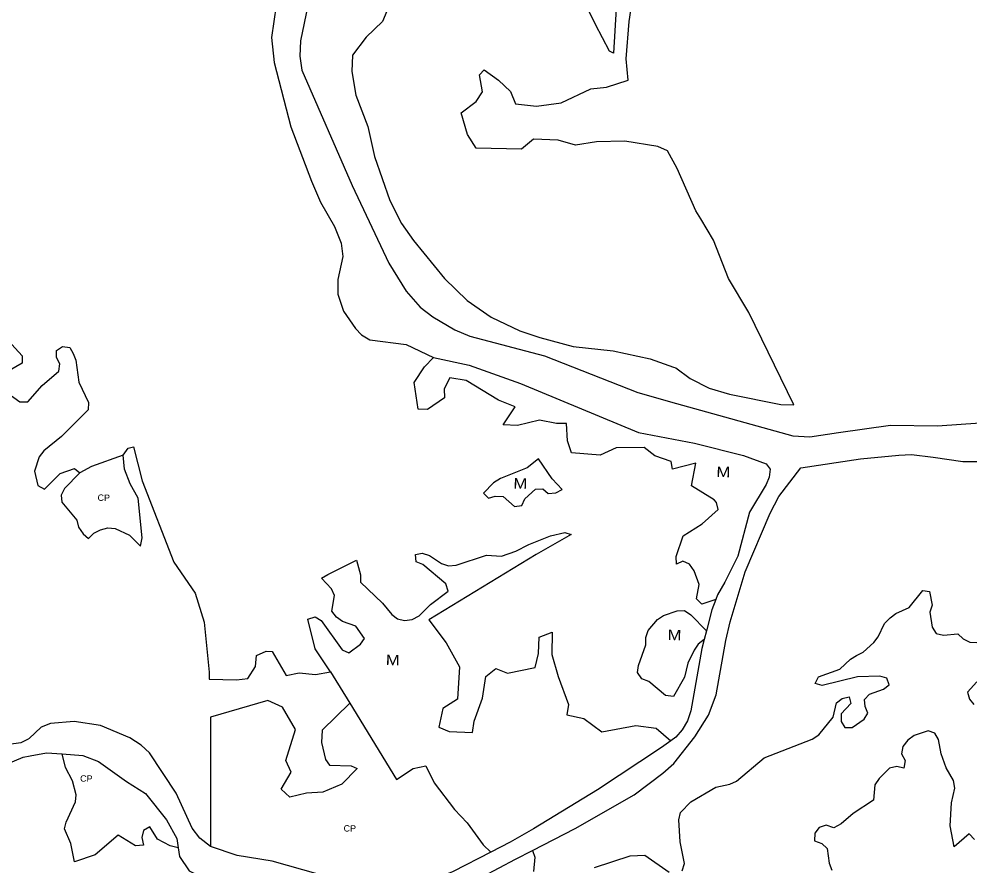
# Model space of a CAD drawing. Extents: x 713589 to 726391, y 7177764 to 7191819.
# Drawn here: x 718159 to 719111, y 7179355 to 7180202 of the extents above; entities that cross this region are included whole.
import ezdxf
from ezdxf.enums import TextEntityAlignment as Align

# ---------------------------------------------------------------- set-up
doc = ezdxf.new("R2010")
doc.units = 0
doc.header["$LTSCALE"] = 2.6
doc.layers.add('63', color=7, linetype='Continuous', lineweight=25)

msp = doc.modelspace()

# ---------------------------------------------------------------- linework, layer by layer
at = {"layer": '63'}
msp.add_line((718846.75, 7179590.09), (718844.48, 7179581.34), dxfattribs=at)
for points in [[(718765.06, 7180358.02), (718753.62, 7180167.91), (718749.67, 7180170), (718735.81, 7180196.62), (718723.68, 7180221.01)], [(718530.19, 7180218.08), (718522.62, 7180199.65), (718506.16, 7180183.86), (718492.67, 7180166.09), (718492.01, 7180149.64), (718495.95, 7180125.94), (718507.79, 7180094.68), (718514.7, 7180064.73), (718529.83, 7180020.64), (718541.67, 7179997.6), (718553.51, 7179980.49), (718584.77, 7179942.64), (718607.14, 7179920.59), (718631.16, 7179903.8), (718660.12, 7179890.3), (718679.86, 7179883.39), (718713.42, 7179874.5), (718753.57, 7179870.21), (718790.42, 7179862.31), (718813.86, 7179853.89), (718816.09, 7179853.09), (718830.57, 7179842.56), (718849.65, 7179832.68), (718869.72, 7179826.75), (718921.06, 7179816.54), (718934.29, 7179816.22), (718889.15, 7179908.36), (718868.76, 7179942.59), (718853.95, 7179980.76), (718841.11, 7180002.18), (718836.19, 7180010.38), (718817.44, 7180052.51), (718807.9, 7180070.28), (718798.03, 7180074.56), (718765.12, 7180079.83), (718736.82, 7180079.17), (718715.76, 7180075.89), (718698.32, 7180080.83), (718673.64, 7180081.82), (718661.79, 7180071.95), (718616.38, 7180072.94), (718607.5, 7180086.44), (718601.25, 7180108.16), (718616.39, 7180119.67), (718622.64, 7180129.21), (718619.68, 7180146.33), (718624.29, 7180151.26), (718638.77, 7180141.06), (718650.61, 7180129.54), (718655.55, 7180117.36), (718676.61, 7180115.05), (718701.29, 7180118.34), (718730.91, 7180132.16), (718746.7, 7180133.8), (718768.42, 7180141.03), (718766.31, 7180162.46), (718769.31, 7180199.74), (718776.89, 7180248.44)], [(718417.78, 7180225.72), (718416.02, 7180215.6), (718411.5, 7180183.76), (718414.1, 7180158.63), (718430.81, 7180094.32), (718451.52, 7180039.92), (718460.36, 7180018.74), (718474.48, 7179994.61), (718481.19, 7179977.94), (718482.95, 7179964.54), (718477.85, 7179941.62), (718478, 7179926.8), (718483.38, 7179909.83), (718495.38, 7179892.46), (718501.65, 7179886), (718510.02, 7179881), (718546.1, 7179876.34), (718573.47, 7179863.35)], [(718447.7, 7180215.62), (718440.47, 7180180.39), (718439.95, 7180165.08), (718441.96, 7180150.95), (718492.24, 7180035.69), (718528.81, 7179958), (718546.27, 7179929.79), (718560.1, 7179914.01), (718573.06, 7179904.29), (718594.95, 7179891.09), (718609.89, 7179884.69), (718684.7, 7179865.16), (718777.95, 7179828.53), (718816.94, 7179817.6), (718933.11, 7179785.01), (718950.1, 7179784.17), (718978.88, 7179788.48), (719030.92, 7179795.77), (719078.16, 7179795.17), (719158.78, 7179800.91)], [(718137.01, 7179892.02), (718161.9, 7179865.05), (718161.9, 7179857.81), (718149.39, 7179850.57)], [(718141.49, 7179832.15), (718159.59, 7179818.98), (718167.48, 7179818.98), (718181.97, 7179835.43), (718198.75, 7179849.91), (718199.74, 7179857.15), (718196.45, 7179863.4), (718196.45, 7179870.64), (718202.37, 7179874.59), (718209.61, 7179873.6), (718212.9, 7179867.35), (718215.54, 7179860.76), (718218.49, 7179838.71), (718228.36, 7179818.31), (718228.03, 7179811.07), (718201.37, 7179784.42), (718183.6, 7179769.95), (718178.99, 7179764.02), (718174.38, 7179749.87), (718177.67, 7179735.39), (718184.25, 7179731.77), (718200.05, 7179747.57), (718214.2, 7179752.5), (718219.79, 7179748.22)], [(718856.09, 7179621.3), (718842.04, 7179616.61), (718836.78, 7179621.88), (718839.41, 7179636.36), (718834.48, 7179650.18), (718829.87, 7179656.76), (718823.29, 7179659.73), (718816.71, 7179656.77), (718816.38, 7179664.33), (718823.63, 7179685.06), (718842.39, 7179696.91), (718858.51, 7179711.38), (718856.87, 7179718.29), (718854.4, 7179720.94), (718831.65, 7179735.24), (718836.08, 7179757.92), (718812.71, 7179751.67), (718811.4, 7179759.57), (718794.95, 7179765.17), (718784.42, 7179773.39), (718756.45, 7179773.07), (718740.32, 7179765.83), (718711.69, 7179768.14), (718707.75, 7179779.99), (718706.76, 7179797.43), (718696.56, 7179797.43), (718679.78, 7179800.72), (718657.73, 7179795.46), (718643.25, 7179796.12), (718655.43, 7179814.22), (718638.65, 7179820.81), (718606.4, 7179840.56), (718589.95, 7179843.19), (718584.42, 7179832.2), (718584.68, 7179823.12), (718567.57, 7179811.6), (718558.35, 7179811.93), (718554.15, 7179838.46), (718564.68, 7179854.25), (718573.47, 7179863.35)], [(718573.47, 7179863.35), (718609.23, 7179855.76), (718660.53, 7179837.63), (718778.85, 7179788.46), (718834.93, 7179777.79), (718883.69, 7179765.27), (718906.44, 7179757.04), (718910.43, 7179751.72), (718909.6, 7179743.91), (718906.51, 7179736.37), (718889.71, 7179708.87), (718878.12, 7179664.67), (718865.13, 7179638.66), (718857.88, 7179626.03), (718856.09, 7179621.3)], [(718263.03, 7179765.87), (718268.17, 7179772.89), (718273.34, 7179774.04), (718282.16, 7179740.11), (718313.74, 7179658.83), (718335.06, 7179627.65), (718335.12, 7179627.56), (718344, 7179598.6), (718348.93, 7179548.58), (718349.18, 7179541.52), (718376.39, 7179541.01), (718387.91, 7179542.32), (718395.48, 7179554.17), (718396.47, 7179565.36), (718406.02, 7179569.63), (718412.27, 7179569.3), (718426.09, 7179545.28), (718439.25, 7179547.91), (718455.37, 7179546.26), (718470.36, 7179548.87)], [(718219.79, 7179748.22), (718204.32, 7179732.43), (718201.03, 7179725.85), (718201.69, 7179718.61), (718216.49, 7179700.83), (718218.47, 7179693.59), (718223.07, 7179687.01), (718228.34, 7179682.4), (718233.6, 7179687.67), (718240.19, 7179690.96), (718247.75, 7179692.93), (718254.99, 7179692.27), (718269.47, 7179685.69), (718280.33, 7179674.83), (718281.98, 7179683.05), (718278.03, 7179722.87), (718270.14, 7179737.02), (718264.22, 7179751.83), (718263.03, 7179765.87)], [(718263.03, 7179765.87), (718231.31, 7179754.27), (718219.79, 7179748.22)], [(718672.71, 7179370.23), (718715.22, 7179392.09), (718774.47, 7179425.8), (718803.17, 7179447.44), (718814.07, 7179457.29), (718835.11, 7179483.83), (718848.71, 7179505.65), (718856.33, 7179525.83), (718866.33, 7179580.24), (718870.5, 7179599), (718885.54, 7179648.93), (718910.68, 7179707.68), (718919.3, 7179724.52), (718941.19, 7179753.05), (719000.97, 7179762.07), (719039.22, 7179765.93), (719052.01, 7179766.42), (719073.8, 7179763.74), (719103.36, 7179759.33), (719158.41, 7179759.27)], [(718470.36, 7179548.87), (718455.29, 7179572.01), (718447.88, 7179601.82), (718455.05, 7179603.85), (718461.31, 7179600.23), (718482.36, 7179570.94), (718488.94, 7179567.97), (718500.46, 7179576.53), (718504.41, 7179582.45), (718495.86, 7179594.63), (718482.37, 7179599.24), (718476.44, 7179603.52), (718471.84, 7179609.77), (718474.47, 7179625.23), (718471.51, 7179632.15), (718461.58, 7179642.78), (718467.74, 7179646.3), (718496.69, 7179660.76), (718500.47, 7179645.96), (718500.47, 7179638.72), (718522.52, 7179617.66), (718532.06, 7179606.47), (718537.65, 7179601.86), (718544.56, 7179600.21), (718552.13, 7179601.2), (718559.37, 7179605.15), (718570.56, 7179616.33), (718588.33, 7179629.82), (718586.03, 7179637.06), (718563, 7179656.48), (718556.09, 7179659.11), (718555.43, 7179666.35), (718562.34, 7179667.67), (718569.58, 7179665.36), (718581.76, 7179657.46), (718588.67, 7179655.16), (718596.23, 7179655.82), (718626.51, 7179665.68), (718641.65, 7179664.69), (718656.13, 7179669.63), (718668.96, 7179676.54), (718690.68, 7179685.09), (718705.16, 7179688.38), (718711.45, 7179686.34), (718676.38, 7179666.33), (718568.89, 7179601.03), (718586.2, 7179578.16), (718599.68, 7179554.13), (718597.53, 7179521.56), (718583.05, 7179512.34), (718579.09, 7179493.59), (718589.29, 7179489.31), (718612.66, 7179488.32), (718614.31, 7179499.51), (718622.54, 7179522.54), (718625.83, 7179544.26), (718636.03, 7179552.48), (718647.55, 7179547.54), (718675.19, 7179553.46), (718678.82, 7179567.28), (718679.48, 7179583.74), (718692.31, 7179588.67), (718691.98, 7179566.29), (718698.23, 7179544.24), (718708.75, 7179516.27), (718707.1, 7179506.07), (718723.89, 7179502.45), (718741.98, 7179488.95), (718776.21, 7179495.2), (718796.28, 7179492.56), (718811.25, 7179480.07)], [(718822.57, 7179350.01), (718824.88, 7179357.24), (718820.6, 7179378.96), (718819.29, 7179401.01), (718820.94, 7179408.25), (718831.14, 7179418.78), (718856.15, 7179433.58), (718870.3, 7179436.54), (718876.89, 7179439.5), (718904.53, 7179462.86), (718952.58, 7179481.61), (718959.16, 7179485.89), (718973.64, 7179503.65), (718976.94, 7179517.8), (718982.53, 7179522.41), (718989.44, 7179524.05), (718991.42, 7179517.14), (718981.54, 7179506.94), (718981.54, 7179499.38), (718985.16, 7179493.12), (718992.73, 7179493.12), (719004.58, 7179501.67), (719008.2, 7179507.6), (719005.57, 7179514.18), (719004.91, 7179521.42), (719009.85, 7179526.68), (719024, 7179531.62), (719029.59, 7179535.89), (719027.29, 7179542.8), (719020.38, 7179544.78), (718998, 7179544.13), (718962.46, 7179535.25), (718955.55, 7179537.22), (718958.84, 7179544.13), (718980.23, 7179551.7), (718990.77, 7179561.57), (718997.02, 7179565.19), (719003.6, 7179568.81), (719014.13, 7179578.35), (719018.74, 7179583.94), (719025, 7179597.43), (719030.59, 7179603.02), (719036.19, 7179607.3), (719049.68, 7179613.22), (719063.17, 7179630.33), (719070.08, 7179629.34), (719072.71, 7179615.52), (719070.41, 7179608.61), (719072.71, 7179593.8), (719076.66, 7179587.22), (719083.9, 7179585.57), (719098.38, 7179586.89), (719103.64, 7179581.95), (719110.22, 7179578.66), (719124.37, 7179578)], [(718856.09, 7179621.3), (718852.15, 7179610.89), (718846.75, 7179590.09)], [(718844.48, 7179581.34), (718838.42, 7179576.8), (718834.47, 7179570.55), (718828.21, 7179557.71), (718824.92, 7179543.56), (718813.73, 7179524.15), (718805.83, 7179525.14), (718789.05, 7179539.29), (718782.14, 7179541.93), (718777.86, 7179548.18), (718778.85, 7179555.42), (718786.09, 7179576.15), (718786.1, 7179583.39), (718788.4, 7179590.3), (718797.94, 7179601.48), (718803.87, 7179605.43), (718817.36, 7179610.04), (718824.93, 7179610.36), (718831.18, 7179606.09), (718846.75, 7179590.09)], [(718844.48, 7179581.34), (718842.12, 7179572.27), (718831.02, 7179509.8), (718827.91, 7179499.93), (718822.59, 7179490.85), (718816.03, 7179483.63), (718811.25, 7179480.07)], [(718470.36, 7179548.87), (718473.12, 7179544.63), (718489.8, 7179517.52)], [(719117.45, 7179538.84), (719107.91, 7179528.64), (719109.88, 7179521.73), (719114.49, 7179516.46)], [(718489.8, 7179517.52), (718462.27, 7179490.65), (718461.61, 7179478.14), (718465.56, 7179461.36), (718469.51, 7179455.76), (718491.23, 7179454.77), (718497.15, 7179452.14), (718482.01, 7179436.68), (718462.92, 7179428.45), (718446.47, 7179427.47), (718429.68, 7179423.52), (718421.13, 7179431.42), (718431, 7179448.53), (718425.74, 7179460.38), (718435.62, 7179491.31), (718422.46, 7179513.69), (718407.65, 7179520.27), (718350.51, 7179503.51), (718350.48, 7179374.31)], [(718489.8, 7179517.52), (718536.66, 7179441.36), (718553.09, 7179452.13), (718565.92, 7179455.09), (718574.15, 7179437.98), (718594.55, 7179411.32), (718607.38, 7179397.82), (718623.17, 7179375.77), (718630.89, 7179368.45)], [(718350.48, 7179374.31), (718339.91, 7179382.49), (718331.92, 7179392.54), (718316.23, 7179427.44), (718289.25, 7179467.8), (718281.1, 7179475.56), (718269.56, 7179482.94), (718240.28, 7179495.16), (718213.93, 7179499.21), (718190.27, 7179497.2), (718180.94, 7179493.61), (718169.11, 7179482.34), (718168.4, 7179481.98)], [(719115, 7179381.15), (719109.72, 7179386.9), (719094.73, 7179373.96), (719090.65, 7179394.97), (719091.97, 7179418.01), (719095.26, 7179432.49), (719093.95, 7179440.39), (719086.71, 7179452.89), (719081.78, 7179467.04), (719079.15, 7179481.19), (719075.2, 7179487.45), (719068.62, 7179490.08), (719054.8, 7179485.15), (719048.21, 7179480.54), (719043.28, 7179474.29), (719041.96, 7179467.05), (719045.58, 7179460.14), (719044.26, 7179452.57), (719037.35, 7179454.22), (719030.11, 7179452.57), (719019.58, 7179442.37), (719015.3, 7179435.79), (719013.98, 7179420.66), (718993.58, 7179407.17), (718981.73, 7179396.97), (718974.16, 7179393.02), (718966.59, 7179395.65), (718959.68, 7179393.35), (718955.4, 7179387.43), (718955.07, 7179379.86), (718962.31, 7179377.23), (718967.57, 7179372.29), (718969.55, 7179357.48), (718972.18, 7179350.57)], [(717854.58, 7179395.17), (717919.62, 7179412.84), (717953.71, 7179424.1), (717989.86, 7179438.24), (718012.44, 7179445.87), (718055.5, 7179460.42), (718107.27, 7179471.36), (718161.03, 7179478.23), (718168.4, 7179481.98)], [(718811.25, 7179480.07), (718801.92, 7179473.12), (718737.65, 7179430.94), (718673.78, 7179391.99), (718650.43, 7179378.42), (718630.89, 7179368.45)], [(717855, 7179382.57), (717941.99, 7179405.15), (717998.88, 7179423.95), (718035.37, 7179435.38), (718085.72, 7179453.72), (718109.09, 7179458.41), (718123.22, 7179454.67), (718130.05, 7179454.57), (718145.63, 7179456.3), (718162.84, 7179463.57), (718169.83, 7179464.89), (718186.43, 7179468.03), (718201.94, 7179466.9)], [(718318.21, 7179372.75), (718310.14, 7179374.95), (718297.47, 7179381.6), (718289.55, 7179393.96), (718283.53, 7179390.16), (718281.63, 7179383.19), (718283.21, 7179375.59), (718275.29, 7179374.95), (718257.94, 7179385.39), (718234.91, 7179365.9), (718214.17, 7179358.89), (718210.67, 7179377.18), (718204.34, 7179391.76), (718205.92, 7179398.73), (718215.43, 7179419), (718216.06, 7179425.97), (718212.26, 7179439.91), (718205.3, 7179453.21), (718201.94, 7179466.9)], [(718201.94, 7179466.9), (718222.57, 7179465.4), (718238.47, 7179459.3), (718266.48, 7179439.21), (718285.46, 7179427.38), (718306.42, 7179400.98), (718316.75, 7179382.09), (718318.21, 7179372.75)], [(718318.21, 7179372.75), (718319.56, 7179364.12), (718329.01, 7179349.91), (718335.11, 7179346.85), (718355.01, 7179341.55)], [(718630.89, 7179368.45), (718593.31, 7179349.29), (718590.38, 7179347.8), (718561.58, 7179337.81), (718547.69, 7179335.36), (718510.76, 7179338.33), (718491.64, 7179339.27), (718473.39, 7179342.21), (718412.17, 7179359.53), (718377, 7179365.12), (718350.48, 7179374.31)], [(718603.73, 7179332.36), (718622.91, 7179344.13), (718655.66, 7179361.46), (718672.71, 7179370.23)], [(718672.71, 7179370.23), (718675.15, 7179363.52), (718673.83, 7179349.04)], [(718734.71, 7179353.31), (718770.58, 7179364.82), (718785.06, 7179365.48), (718809.41, 7179348.69)]]:
    msp.add_lwpolyline(points, dxfattribs=at)
msp.add_lwpolyline([(718662.06, 7179715.37), (718665.02, 7179721.95), (718675.55, 7179731.82), (718683.12, 7179732.15), (718688.39, 7179727.54), (718695.96, 7179728.19), (718702.21, 7179731.48), (718692.34, 7179742.02), (718678.74, 7179762.08), (718667.33, 7179753.21), (718640.67, 7179742.35), (718633.76, 7179738.08), (718623.56, 7179727.88), (718628.49, 7179722.61), (718635.41, 7179724.59), (718643.3, 7179724.26), (718654.82, 7179714.38)], close=True, dxfattribs=at)

# ---------------------------------------------------------------- texts
for s, height, width, p in [('M', 10.4, 1.2, (718863.63, 7179743.79)), ('M', 10.4, 1.2, (718660.48, 7179732.29)), ('CP', 6.4, 1.05, (718243.56, 7179719.99)), ('M', 10.4, 1.2, (718814.77, 7179580.6)), ('M', 10.4, 1.2, (718532.74, 7179555.63)), ('CP', 6.4, 1.05, (718226.14, 7179439.03)), ('CP', 6.4, 1.05, (718489.79, 7179389.12))]:
    msp.add_text(s, height=height, rotation=359.062, dxfattribs=dict(at, width=width)).set_placement(p, align=Align.CENTER)

doc.saveas('drawing.dxf')
